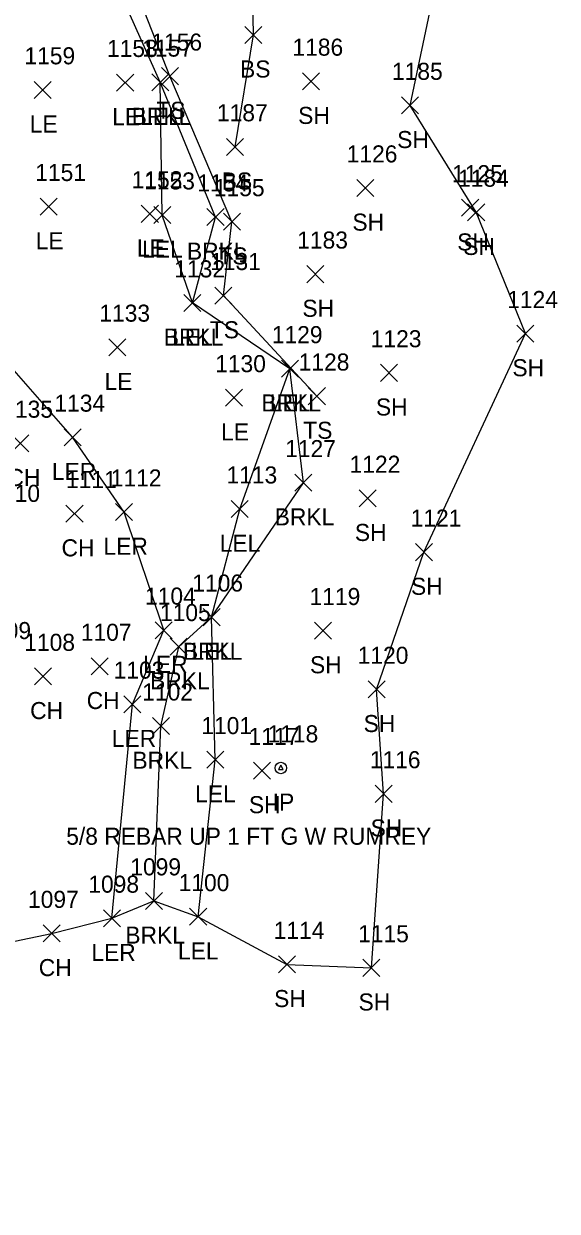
# Model space of a CAD drawing. Extents: x 1651685 to 1653558, y 889533 to 891085.
# Drawn here: x 1652731 to 1652793.5, y 890075.4 to 890214.6 of the extents above; entities that cross this region are included whole.
import ezdxf

# ---------------------------------------------------------------- set-up
doc = ezdxf.new("R2010")
doc.units = 0
for name, color, linetype in [('L_A', 7, 'Continuous'), ('L_I', 7, 'Continuous'), ('L_TIC', 7, 'Continuous'), ('LARO', 7, 'Continuous'), ('LAWE', 7, 'Continuous'), ('LELB', 7, 'Continuous'), ('LSOGP', 7, 'Continuous'), ('M_A', 7, 'Continuous'), ('M_C', 7, 'Continuous'), ('M_I', 7, 'Continuous'), ('MPIR', 7, 'Continuous')]:
    doc.layers.add(name, color=color, linetype=linetype)

msp = doc.modelspace()

# ---------------------------------------------------------------- linework, layer by layer
at = {"layer": 'L_TIC'}
for points in [[(1652756.87, 890212.31), (1652758.87, 890214.31)], [(1652758.87, 890212.31), (1652756.87, 890214.31)], [(1652747.09, 890207.47), (1652749.09, 890209.47)], [(1652749.09, 890207.47), (1652747.09, 890209.47)], [(1652741.84, 890206.72), (1652743.84, 890208.72)], [(1652743.84, 890206.72), (1652741.84, 890208.72)], [(1652745.95, 890206.76), (1652747.95, 890208.76)], [(1652747.95, 890206.76), (1652745.95, 890208.76)], [(1652745.95, 890206.76), (1652747.95, 890208.76)], [(1652747.95, 890206.76), (1652745.95, 890208.76)], [(1652763.63, 890206.87), (1652765.63, 890208.87)], [(1652765.63, 890206.87), (1652763.63, 890208.87)], [(1652732.16, 890205.86), (1652734.16, 890207.86)], [(1652734.16, 890205.86), (1652732.16, 890207.86)], [(1652775.25, 890204.04), (1652777.25, 890206.04)], [(1652777.25, 890204.04), (1652775.25, 890206.04)], [(1652754.73, 890199.18), (1652756.73, 890201.18)], [(1652756.73, 890199.18), (1652754.73, 890201.18)], [(1652769.99, 890194.36), (1652771.99, 890196.36)], [(1652771.99, 890194.36), (1652769.99, 890196.36)], [(1652732.86, 890192.18), (1652734.86, 890194.18)], [(1652734.86, 890192.18), (1652732.86, 890194.18)], [(1652782.29, 890192.04), (1652784.29, 890194.04)], [(1652784.29, 890192.04), (1652782.29, 890194.04)], [(1652744.73, 890191.33), (1652746.73, 890193.33)], [(1652746.73, 890191.33), (1652744.73, 890193.33)], [(1652746.19, 890191.19), (1652748.19, 890193.19)], [(1652748.19, 890191.19), (1652746.19, 890193.19)], [(1652752.43, 890190.96), (1652754.43, 890192.96)], [(1652754.43, 890190.96), (1652752.43, 890192.96)], [(1652782.99, 890191.51), (1652784.99, 890193.51)], [(1652784.99, 890191.51), (1652782.99, 890193.51)], [(1652754.36, 890190.4), (1652756.36, 890192.4)], [(1652756.36, 890190.4), (1652754.36, 890192.4)], [(1652764.13, 890184.26), (1652766.13, 890186.26)], [(1652766.13, 890184.26), (1652764.13, 890186.26)], [(1652749.72, 890180.88), (1652751.72, 890182.88)], [(1652751.72, 890180.88), (1652749.72, 890182.88)], [(1652749.72, 890180.88), (1652751.72, 890182.88)], [(1652751.72, 890180.88), (1652749.72, 890182.88)], [(1652753.36, 890181.74), (1652755.36, 890183.74)], [(1652755.36, 890181.74), (1652753.36, 890183.74)], [(1652788.75, 890177.29), (1652790.75, 890179.29)], [(1652790.75, 890177.29), (1652788.75, 890179.29)], [(1652740.93, 890175.69), (1652742.93, 890177.69)], [(1652742.93, 890175.69), (1652740.93, 890177.69)], [(1652761.16, 890173.17), (1652763.16, 890175.17)], [(1652763.16, 890173.17), (1652761.16, 890175.17)], [(1652761.16, 890173.17), (1652763.16, 890175.17)], [(1652763.16, 890173.17), (1652761.16, 890175.17)], [(1652772.76, 890172.69), (1652774.76, 890174.69)], [(1652774.76, 890172.69), (1652772.76, 890174.69)], [(1652754.6, 890169.77), (1652756.6, 890171.77)], [(1652756.6, 890169.77), (1652754.6, 890171.77)], [(1652764.31, 890169.96), (1652766.31, 890171.96)], [(1652766.31, 890169.96), (1652764.31, 890171.96)], [(1652729.56, 890164.43), (1652731.56, 890166.43)], [(1652731.56, 890164.43), (1652729.56, 890166.43)], [(1652735.67, 890165.14), (1652737.67, 890167.14)], [(1652737.67, 890165.14), (1652735.67, 890167.14)], [(1652762.73, 890159.81), (1652764.73, 890161.81)], [(1652764.73, 890159.81), (1652762.73, 890161.81)], [(1652770.28, 890157.98), (1652772.28, 890159.98)], [(1652772.28, 890157.98), (1652770.28, 890159.98)], [(1652735.9, 890156.18), (1652737.9, 890158.18)], [(1652737.9, 890156.18), (1652735.9, 890158.18)], [(1652741.71, 890156.37), (1652743.71, 890158.37)], [(1652743.71, 890156.37), (1652741.71, 890158.37)], [(1652755.28, 890156.72), (1652757.28, 890158.72)], [(1652757.28, 890156.72), (1652755.28, 890158.72)], [(1652776.86, 890151.67), (1652778.86, 890153.67)], [(1652778.86, 890151.67), (1652776.86, 890153.67)], [(1652751.97, 890144.05), (1652753.97, 890146.05)], [(1652753.97, 890144.05), (1652751.97, 890146.05)], [(1652751.97, 890144.05), (1652753.97, 890146.05)], [(1652753.97, 890144.05), (1652751.97, 890146.05)], [(1652746.37, 890142.52), (1652748.37, 890144.52)], [(1652748.37, 890142.52), (1652746.37, 890144.52)], [(1652765.02, 890142.47), (1652767.02, 890144.47)], [(1652767.02, 890142.47), (1652765.02, 890144.47)], [(1652748.12, 890140.59), (1652750.12, 890142.59)], [(1652750.12, 890140.59), (1652748.12, 890142.59)], [(1652738.84, 890138.28), (1652740.84, 890140.28)], [(1652740.84, 890138.28), (1652738.84, 890140.28)], [(1652732.21, 890137.1), (1652734.21, 890139.1)], [(1652734.21, 890137.1), (1652732.21, 890139.1)], [(1652771.32, 890135.58), (1652773.32, 890137.58)], [(1652773.32, 890135.58), (1652771.32, 890137.58)], [(1652742.69, 890133.84), (1652744.69, 890135.84)], [(1652744.69, 890133.84), (1652742.69, 890135.84)], [(1652746.04, 890131.28), (1652748.04, 890133.28)], [(1652748.04, 890131.28), (1652746.04, 890133.28)], [(1652752.4, 890127.34), (1652754.4, 890129.34)], [(1652754.4, 890127.34), (1652752.4, 890129.34)], [(1652757.87, 890126.07), (1652759.87, 890128.07)], [(1652759.87, 890126.07), (1652757.87, 890128.07)], [(1652772.14, 890123.34), (1652774.14, 890125.34)], [(1652774.14, 890123.34), (1652772.14, 890125.34)], [(1652745.22, 890110.78), (1652747.22, 890112.78)], [(1652747.22, 890110.78), (1652745.22, 890112.78)], [(1652740.29, 890108.75), (1652742.29, 890110.75)], [(1652742.29, 890108.75), (1652740.29, 890110.75)], [(1652750.4, 890108.93), (1652752.4, 890110.93)], [(1652752.4, 890108.93), (1652750.4, 890110.93)], [(1652733.22, 890106.97), (1652735.22, 890108.97)], [(1652735.22, 890106.97), (1652733.22, 890108.97)], [(1652760.81, 890103.34), (1652762.81, 890105.34)], [(1652762.81, 890103.34), (1652760.81, 890105.34)], [(1652770.71, 890102.94), (1652772.71, 890104.94)], [(1652772.71, 890102.94), (1652770.71, 890104.94)]]:
    msp.add_lwpolyline(points, dxfattribs=at)
at = {"layer": 'LARO'}
for points in [[(1652741.29, 890109.75), (1652743.69, 890134.84), (1652747.37, 890143.52), (1652742.71, 890157.37), (1652736.67, 890166.14), (1652716.94, 890188.64), (1652716.7, 890208.34), (1652726.42, 890223.05), (1652732.2, 890229)], [(1652751.4, 890109.93), (1652753.4, 890128.34), (1652752.97, 890145.05), (1652756.28, 890157.72), (1652762.16, 890174.17), (1652750.72, 890181.88), (1652747.19, 890192.19), (1652746.95, 890207.76), (1652740.41, 890222.38), (1652732.2, 890229)]]:
    msp.add_lwpolyline(points, dxfattribs=at)
at = {"layer": 'LAWE'}
for points in [[(1652750.72, 890181.88), (1652753.43, 890191.96), (1652746.95, 890207.76)], [(1652746.22, 890111.78), (1652747.04, 890132.28), (1652749.12, 890141.59), (1652752.97, 890145.05), (1652763.73, 890160.81), (1652762.16, 890174.17)]]:
    msp.add_lwpolyline(points, dxfattribs=at)
at = {"layer": 'LELB'}
for points in [[(1652755.73, 890200.18), (1652757.87, 890213.31), (1652757.55, 890232.11), (1652757.71, 890235.44), (1652763.17, 890255.77), (1652762.15, 890261.51)], [(1652765.31, 890170.96), (1652754.36, 890182.74), (1652755.36, 890191.4), (1652748.09, 890208.47), (1652742.23, 890223.44)]]:
    msp.add_lwpolyline(points, dxfattribs=at)
at = {"layer": 'LSOGP'}
msp.add_lwpolyline([(1652616.64, 890057.03), (1652642.24, 890083.82), (1652665.45, 890109.51), (1652678.8, 890111.5), (1652692.53, 890109.91), (1652706.56, 890112.43), (1652710.52, 890110.8), (1652727.24, 890106.51), (1652734.22, 890107.97), (1652741.29, 890109.75), (1652746.22, 890111.78), (1652751.4, 890109.93), (1652761.81, 890104.34), (1652771.71, 890103.93), (1652773.14, 890124.34), (1652772.32, 890136.58), (1652777.87, 890152.67), (1652789.76, 890178.29), (1652783.99, 890192.51), (1652776.24, 890205.05), (1652781.97, 890232.17)], dxfattribs=at)
at = {"layer": 'MPIR'}
msp.add_lwpolyline([(1652761.09, 890127.7), (1652760.8, 890127.2), (1652761.38, 890127.2)], close=True, dxfattribs=at)
msp.add_circle((1652761.09, 890127.37), 0.667, dxfattribs=at)

# ---------------------------------------------------------------- texts
at = {"layer": 'L_A'}
for s, p in [('BS', (1652756.31, 890208.31)), ('TS', (1652746.5, 890203.47)), ('LE', (1652731.65, 890201.86)), ('LE', (1652741.32, 890202.72)), ('BRKL', (1652743.6, 890202.76)), ('LEL', (1652744.59, 890202.76)), ('SH', (1652763.12, 890202.87)), ('SH', (1652774.73, 890200.04)), ('BS', (1652754.17, 890195.18)), ('SH', (1652769.48, 890190.36)), ('LE', (1652732.35, 890188.18)), ('SH', (1652781.77, 890188.04)), ('LE', (1652744.22, 890187.33)), ('LEL', (1652744.83, 890187.19)), ('BRKL', (1652750.08, 890186.96)), ('TS', (1652753.77, 890186.4)), ('SH', (1652782.48, 890187.51)), ('SH', (1652763.62, 890180.26)), ('BRKL', (1652747.37, 890176.88)), ('LEL', (1652748.36, 890176.88)), ('TS', (1652752.77, 890177.74)), ('SH', (1652788.24, 890173.29)), ('LE', (1652740.42, 890171.69)), ('BRKL', (1652758.81, 890169.17)), ('LEL', (1652759.8, 890169.17)), ('SH', (1652772.24, 890168.69)), ('LE', (1652754.09, 890165.77)), ('TS', (1652763.72, 890165.96)), ('CH', (1652729.04, 890160.43)), ('LER', (1652734.25, 890161.14)), ('BRKL', (1652760.37, 890155.81)), ('SH', (1652769.77, 890153.98)), ('CH', (1652735.38, 890152.18)), ('LER', (1652740.3, 890152.37)), ('LEL', (1652753.92, 890152.72)), ('SH', (1652776.35, 890147.67)), ('BRKL', (1652749.61, 890140.05)), ('LEL', (1652750.61, 890140.05)), ('LER', (1652744.95, 890138.52)), ('SH', (1652764.51, 890138.47)), ('BRKL', (1652745.77, 890136.59)), ('CH', (1652738.33, 890134.28)), ('CH', (1652731.7, 890133.1)), ('SH', (1652770.8, 890131.58)), ('LER', (1652741.27, 890129.84)), ('BRKL', (1652743.69, 890127.28)), ('LEL', (1652751.04, 890123.34)), ('SH', (1652757.35, 890122.07)), ('SH', (1652771.62, 890119.34)), ('BRKL', (1652742.86, 890106.78)), ('LER', (1652738.87, 890104.75)), ('LEL', (1652749.03, 890104.93)), ('CH', (1652732.71, 890102.97)), ('SH', (1652760.3, 890099.34)), ('SH', (1652770.2, 890098.94))]:
    msp.add_text(s, height=2, dxfattribs=at).set_placement(p)
at = {"layer": 'L_I'}
for s, p in [('1156', (1652745.91, 890211.47)), ('1158', (1652740.71, 890210.72)), ('1157', (1652744.83, 890210.76)), ('1157', (1652744.83, 890210.76)), ('1186', (1652762.45, 890210.87)), ('1159', (1652731.03, 890209.86)), ('1185', (1652774.12, 890208.04)), ('1187', (1652753.6, 890203.18)), ('1126', (1652768.81, 890198.36)), ('1151', (1652732.3, 890196.18)), ('1152', (1652743.6, 890195.33)), ('1153', (1652745.07, 890195.19)), ('1154', (1652751.31, 890194.96)), ('1125', (1652781.16, 890196.04)), ('1184', (1652781.87, 890195.51)), ('1155', (1652753.24, 890194.4)), ('1183', (1652763.01, 890188.26)), ('1131', (1652752.8, 890185.74)), ('1132', (1652748.6, 890184.88)), ('1132', (1652748.6, 890184.88)), ('1124', (1652787.63, 890181.29)), ('1133', (1652739.81, 890179.69)), ('1129', (1652760.03, 890177.17)), ('1129', (1652760.03, 890177.17)), ('1123', (1652771.63, 890176.69)), ('1128', (1652763.18, 890173.96)), ('1130', (1652753.39, 890173.77)), ('1135', (1652728.43, 890168.43)), ('1134', (1652734.54, 890169.14)), ('1127', (1652761.6, 890163.81)), ('1122', (1652769.15, 890161.98)), ('1111', (1652735.9, 890160.18)), ('1112', (1652741.15, 890160.37)), ('1113', (1652754.72, 890160.72)), ('1110', (1652726.91, 890158.56)), ('1121', (1652776.31, 890155.67)), ('1106', (1652750.71, 890148.05)), ('1106', (1652750.71, 890148.05)), ('1104', (1652745.17, 890146.52)), ('1119', (1652764.46, 890146.47)), ('1105', (1652746.92, 890144.59)), ('1109', (1652725.86, 890142.48)), ('1107', (1652737.64, 890142.28)), ('1108', (1652731.01, 890141.1)), ('1120', (1652770.1, 890139.58)), ('1103', (1652741.49, 890137.84)), ('1102', (1652744.84, 890135.28)), ('1101', (1652751.77, 890131.34)), ('1117', (1652757.31, 890130.07)), ('1116', (1652771.52, 890127.34)), ('1099', (1652743.44, 890114.78)), ('1098', (1652738.52, 890112.75)), ('1100', (1652749.11, 890112.93)), ('1097', (1652731.45, 890110.97)), ('1114', (1652760.25, 890107.34)), ('1115', (1652770.15, 890106.94))]:
    msp.add_text(s, height=2, dxfattribs=at).set_placement(p)
at = {"layer": 'M_A'}
msp.add_text('IP', height=2, dxfattribs=at).set_placement((1652760.14, 890122.37))
at = {"layer": 'M_C'}
msp.add_text('5/8 REBAR UP 1 FT G W RUMREY', height=2, dxfattribs=at).set_placement((1652735.93, 890118.37))
at = {"layer": 'M_I'}
msp.add_text('1118', height=2, dxfattribs=at).set_placement((1652759.53, 890130.37))

doc.saveas('drawing.dxf')
